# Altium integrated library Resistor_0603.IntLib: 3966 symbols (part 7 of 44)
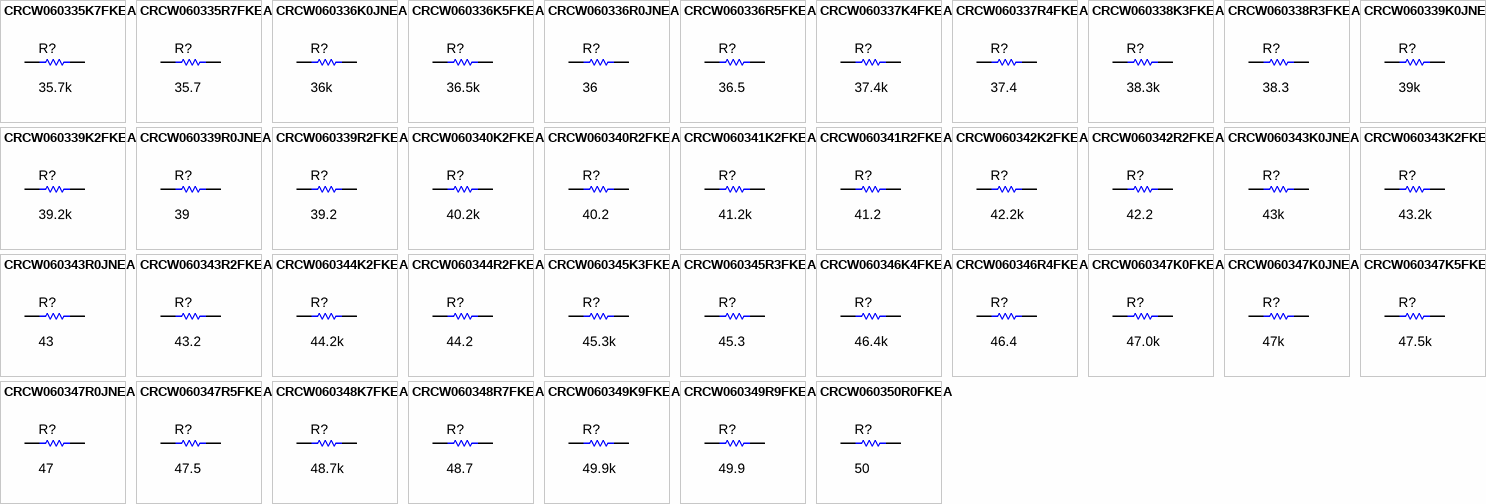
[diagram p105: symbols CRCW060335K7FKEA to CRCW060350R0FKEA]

## CRCW060342K2FKEA
designator R?  ValueDisplayed: 42.2k  (hidden comment: CRCW060342K2FKEA)
RES, 42.2 k, 1%, 0.1 W, 0603; Manufacturer: Vishay-Dale; CompType: Resistor; Value: 42.2k; Res_ohm: 42200; Value_Code: 42k2; Tolerance_%: 1; Power_W: 0.1; Value2: 0.1W; VDC_V: 75; TempCo: 100 ppm/C; SizeArea_mm2: 1.28; SizeX_mm: 1.6; SizeY_mm: 0.8; EIA_Code: E96; U/M: EA; AEC Category: Q200; Green_Lifecycle: Active; Green_REACh: Passed
signal-integrity model Resistor
simulation model Resistor
footprint 0603
footprint 0603M
footprint 0603L
footprint 0603_HV
footprint 0603S
pins: 1, 2

## CRCW060342R2FKEA
designator R?  ValueDisplayed: 42.2  (hidden comment: CRCW060342R2FKEA)
RES, 42.2, 1%, 0.1 W, 0603; Manufacturer: Vishay-Dale; CompType: Resistor; Value: 42.2; Value_Code: 42R2; Tolerance_%: 1; Power_W: 0.1; Value2: 0.1W; VDC_V: 75; TempCo: 100 ppm/C; SizeArea_mm2: 1.28; SizeX_mm: 1.6; SizeY_mm: 0.8; EIA_Code: E96; U/M: EA; AEC Category: Q200
signal-integrity model Resistor
simulation model Resistor
footprint 0603
footprint 0603M
footprint 0603L
footprint 0603_HV
footprint 0603S
pins: 1, 2

## CRCW060343K0JNEA
designator R?  ValueDisplayed: 43k  (hidden comment: CRCW060343K0JNEA)
RES, 43 k, 5%, 0.1 W, 0603; Manufacturer: Vishay-Dale; CompType: Resistor; Value: 43k; Res_ohm: 43000; Value_Code: 43k0; Tolerance_%: 5; Power_W: 0.1; Value2: 0.1W; VDC_V: 75; TempCo: 200 ppm/C; SizeArea_mm2: 1.28; SizeX_mm: 1.6; SizeY_mm: 0.8; SizeZ_mm: 1; EIA_Code: E24; U/M: EA; AEC Category: Q200
signal-integrity model Resistor
simulation model Resistor
footprint 0603
footprint 0603M
footprint 0603L
footprint 0603_HV
footprint 0603S
pins: 1, 2

## CRCW060343K2FKEA
designator R?  ValueDisplayed: 43.2k  (hidden comment: CRCW060343K2FKEA)
RES, 43.2 k, 1%, 0.1 W, 0603; Manufacturer: Vishay-Dale; CompType: Resistor; Value: 43.2k; Res_ohm: 43200; Value_Code: 43k2; Tolerance_%: 1; Power_W: 0.1; Value2: 0.1W; VDC_V: 75; TempCo: 100 ppm/C; SizeArea_mm2: 1.28; SizeX_mm: 1.6; SizeY_mm: 0.8; EIA_Code: E96; U/M: EA; AEC Category: Q200; Green_Lifecycle: Active; Green_REACh: Passed
signal-integrity model Resistor
simulation model Resistor
footprint 0603
footprint 0603M
footprint 0603L
footprint 0603_HV
footprint 0603S
pins: 1, 2

## CRCW060343R0JNEA
designator R?  ValueDisplayed: 43  (hidden comment: CRCW060343R0JNEA)
RES, 43, 5%, 0.1 W, 0603; Manufacturer: Vishay-Dale; CompType: Resistor; Value: 43; Value_Code: 43R0; Tolerance_%: 5; Power_W: 0.1; Value2: 0.1W; VDC_V: 75; TempCo: 200 ppm/C; SizeArea_mm2: 1.28; SizeX_mm: 1.6; SizeY_mm: 0.8; SizeZ_mm: 1; EIA_Code: E24; U/M: EA; AEC Category: Q200; Green_Lifecycle: Active; Green_REACh: Passed
signal-integrity model Resistor
simulation model Resistor
footprint 0603
footprint 0603M
footprint 0603L
footprint 0603_HV
footprint 0603S
pins: 1, 2

## CRCW060343R2FKEA
designator R?  ValueDisplayed: 43.2  (hidden comment: CRCW060343R2FKEA)
RES, 43.2, 1%, 0.1 W, 0603; Manufacturer: Vishay-Dale; CompType: Resistor; Value: 43.2; Value_Code: 43R2; Tolerance_%: 1; Power_W: 0.1; Value2: 0.1W; VDC_V: 75; TempCo: 100 ppm/C; SizeArea_mm2: 1.28; SizeX_mm: 1.6; SizeY_mm: 0.8; EIA_Code: E96; U/M: EA; AEC Category: Q200; Green_Lifecycle: Active; Green_REACh: Passed
signal-integrity model Resistor
simulation model Resistor
footprint 0603
footprint 0603M
footprint 0603L
footprint 0603_HV
footprint 0603S
pins: 1, 2

## CRCW060344K2FKEA
designator R?  ValueDisplayed: 44.2k  (hidden comment: CRCW060344K2FKEA)
RES, 44.2 k, 1%, 0.1 W, 0603; Manufacturer: Vishay-Dale; CompType: Resistor; Value: 44.2k; Res_ohm: 44200; Value_Code: 44k2; Tolerance_%: 1; Power_W: 0.1; Value2: 0.1W; VDC_V: 75; TempCo: 100 ppm/C; SizeArea_mm2: 1.28; SizeX_mm: 1.6; SizeY_mm: 0.8; EIA_Code: E96; U/M: EA; AEC Category: Q200; Green_Lifecycle: Active; Green_REACh: Passed
signal-integrity model Resistor
simulation model Resistor
footprint 0603
footprint 0603M
footprint 0603L
footprint 0603_HV
footprint 0603S
pins: 1, 2

## CRCW060344R2FKEA
designator R?  ValueDisplayed: 44.2  (hidden comment: CRCW060344R2FKEA)
RES, 44.2, 1%, 0.1 W, 0603; Manufacturer: Vishay-Dale; CompType: Resistor; Value: 44.2; Value_Code: 44R2; Tolerance_%: 1; Power_W: 0.1; Value2: 0.1W; VDC_V: 75; TempCo: 100 ppm/C; SizeArea_mm2: 1.28; SizeX_mm: 1.6; SizeY_mm: 0.8; EIA_Code: E96; U/M: EA; AEC Category: Q200
signal-integrity model Resistor
simulation model Resistor
footprint 0603
footprint 0603M
footprint 0603L
footprint 0603_HV
footprint 0603S
pins: 1, 2

## CRCW060345K3FKEA
designator R?  ValueDisplayed: 45.3k  (hidden comment: CRCW060345K3FKEA)
RES, 45.3 k, 1%, 0.1 W, 0603; Manufacturer: Vishay-Dale; CompType: Resistor; Value: 45.3k; Res_ohm: 45300; Value_Code: 45k3; Tolerance_%: 1; Power_W: 0.1; Value2: 0.1W; VDC_V: 75; TempCo: 100 ppm/C; SizeArea_mm2: 1.28; SizeX_mm: 1.6; SizeY_mm: 0.8; EIA_Code: E96; U/M: EA; AEC Category: Q200; Green_Lifecycle: Active; Green_REACh: Passed
signal-integrity model Resistor
simulation model Resistor
footprint 0603
footprint 0603M
footprint 0603L
footprint 0603_HV
footprint 0603S
pins: 1, 2

## CRCW060345R3FKEA
designator R?  ValueDisplayed: 45.3  (hidden comment: CRCW060345R3FKEA)
RES, 45.3, 1%, 0.1 W, 0603; Manufacturer: Vishay-Dale; CompType: Resistor; Value: 45.3; Value_Code: 45R3; Tolerance_%: 1; Power_W: 0.1; Value2: 0.1W; VDC_V: 75; TempCo: 100 ppm/C; SizeArea_mm2: 1.28; SizeX_mm: 1.6; SizeY_mm: 0.8; EIA_Code: E96; U/M: EA; AEC Category: Q200
signal-integrity model Resistor
simulation model Resistor
footprint 0603
footprint 0603M
footprint 0603L
footprint 0603_HV
footprint 0603S
pins: 1, 2

## CRCW060346K4FKEA
designator R?  ValueDisplayed: 46.4k  (hidden comment: CRCW060346K4FKEA)
RES, 46.4 k, 1%, 0.1 W, 0603; Manufacturer: Vishay-Dale; CompType: Resistor; Value: 46.4k; Res_ohm: 46400; Value_Code: 46k4; Tolerance_%: 1; Power_W: 0.1; Value2: 0.1W; VDC_V: 75; TempCo: 100 ppm/C; SizeArea_mm2: 1.28; SizeX_mm: 1.6; SizeY_mm: 0.8; EIA_Code: E96; U/M: EA; AEC Category: Q200; Green_Lifecycle: Active; Green_REACh: Passed
signal-integrity model Resistor
simulation model Resistor
footprint 0603
footprint 0603M
footprint 0603L
footprint 0603_HV
footprint 0603S
pins: 1, 2

## CRCW060346R4FKEA
designator R?  ValueDisplayed: 46.4  (hidden comment: CRCW060346R4FKEA)
RES, 46.4, 1%, 0.1 W, 0603; Manufacturer: Vishay-Dale; CompType: Resistor; Value: 46.4; Value_Code: 46R4; Tolerance_%: 1; Power_W: 0.1; Value2: 0.1W; VDC_V: 75; TempCo: 100 ppm/C; SizeArea_mm2: 1.28; SizeX_mm: 1.6; SizeY_mm: 0.8; EIA_Code: E96; U/M: EA; AEC Category: Q200
signal-integrity model Resistor
simulation model Resistor
footprint 0603
footprint 0603M
footprint 0603L
footprint 0603_HV
footprint 0603S
pins: 1, 2

## CRCW060347K0FKEA
designator R?  ValueDisplayed: 47.0k  (hidden comment: CRCW060347K0FKEA)
RES, 47.0 k, 1%, 0.1 W, AEC-Q200 Grade 0, 0603; Manufacturer: Vishay-Dale; CompType: Resistor; Value: 47.0k; Res_ohm: 47000; Value_Code: 47k0; Tolerance_%: 1; Power_W: 0.1; Value2: 0.1W; VDC_V: 75; TempCo: 100 ppm/C; SizeArea_mm2: 1.28; SizeX_mm: 1.6; SizeY_mm: 0.8; U/M: EA; AEC Category: Q200; AEC Qualified: Y; AEC Grade: 0
signal-integrity model Resistor
simulation model Resistor
footprint 0603
footprint 0603M
footprint 0603L
footprint 0603_HV
footprint 0603S
pins: 1, 2

## CRCW060347K0JNEA
designator R?  ValueDisplayed: 47k  (hidden comment: CRCW060347K0JNEA)
RES, 47 k, 5%, 0.1 W, 0603; Manufacturer: Vishay-Dale; CompType: Resistor; Value: 47k; Res_ohm: 47000; Value_Code: 47k0; Tolerance_%: 5; Power_W: 0.1; Value2: 0.1W; VDC_V: 75; TempCo: 200 ppm/C; SizeArea_mm2: 1.28; SizeX_mm: 1.6; SizeY_mm: 0.8; SizeZ_mm: 1; EIA_Code: E24; U/M: EA; AEC Category: Q200; Green_Lifecycle: Active; Green_REACh: Passed
signal-integrity model Resistor
simulation model Resistor
footprint 0603
footprint 0603M
footprint 0603L
footprint 0603_HV
footprint 0603S
pins: 1, 2

## CRCW060347K5FKEA
designator R?  ValueDisplayed: 47.5k  (hidden comment: CRCW060347K5FKEA)
RES, 47.5 k, 1%, 0.1 W, 0603; Manufacturer: Vishay-Dale; CompType: Resistor; Value: 47.5k; Res_ohm: 47500; Value_Code: 47k5; Tolerance_%: 1; Power_W: 0.1; Value2: 0.1W; VDC_V: 75; TempCo: 100 ppm/C; SizeArea_mm2: 1.28; SizeX_mm: 1.6; SizeY_mm: 0.8; EIA_Code: E96; U/M: EA; AEC Category: Q200; Green_Lifecycle: Active; Green_REACh: Passed
signal-integrity model Resistor
simulation model Resistor
footprint 0603
footprint 0603M
footprint 0603L
footprint 0603_HV
footprint 0603S
pins: 1, 2

## CRCW060347R0JNEA
designator R?  ValueDisplayed: 47  (hidden comment: CRCW060347R0JNEA)
RES, 47, 5%, 0.1 W, 0603; Manufacturer: Vishay-Dale; CompType: Resistor; Value: 47; Value_Code: 47R0; Tolerance_%: 5; Power_W: 0.1; Value2: 0.1W; VDC_V: 75; TempCo: 200 ppm/C; SizeArea_mm2: 1.28; SizeX_mm: 1.6; SizeY_mm: 0.8; SizeZ_mm: 1; EIA_Code: E24; U/M: EA; AEC Category: Q200; Green_Lifecycle: Active; Green_REACh: Passed
signal-integrity model Resistor
simulation model Resistor
footprint 0603
footprint 0603M
footprint 0603L
footprint 0603_HV
footprint 0603S
pins: 1, 2

## CRCW060347R5FKEA
designator R?  ValueDisplayed: 47.5  (hidden comment: CRCW060347R5FKEA)
RES, 47.5, 1%, 0.1 W, 0603; Manufacturer: Vishay-Dale; CompType: Resistor; Value: 47.5; Value_Code: 47R5; Tolerance_%: 1; Power_W: 0.1; Value2: 0.1W; VDC_V: 75; TempCo: 100 ppm/C; SizeArea_mm2: 1.28; SizeX_mm: 1.6; SizeY_mm: 0.8; EIA_Code: E96; U/M: EA; AEC Category: Q200
signal-integrity model Resistor
simulation model Resistor
footprint 0603
footprint 0603M
footprint 0603L
footprint 0603_HV
footprint 0603S
pins: 1, 2

## CRCW060348K7FKEA
designator R?  ValueDisplayed: 48.7k  (hidden comment: CRCW060348K7FKEA)
RES, 48.7 k, 1%, 0.1 W, 0603; Manufacturer: Vishay-Dale; CompType: Resistor; Value: 48.7k; Res_ohm: 48700; Value_Code: 48k7; Tolerance_%: 1; Power_W: 0.1; Value2: 0.1W; VDC_V: 75; TempCo: 100 ppm/C; SizeArea_mm2: 1.28; SizeX_mm: 1.6; SizeY_mm: 0.8; EIA_Code: E96; U/M: EA; AEC Category: Q200; Green_Lifecycle: Active; Green_REACh: Passed
signal-integrity model Resistor
simulation model Resistor
footprint 0603
footprint 0603M
footprint 0603L
footprint 0603_HV
footprint 0603S
pins: 1, 2

## CRCW060348R7FKEA
designator R?  ValueDisplayed: 48.7  (hidden comment: CRCW060348R7FKEA)
RES, 48.7, 1%, 0.1 W, 0603; Manufacturer: Vishay-Dale; CompType: Resistor; Value: 48.7; Value_Code: 48R7; Tolerance_%: 1; Power_W: 0.1; Value2: 0.1W; VDC_V: 75; TempCo: 100 ppm/C; SizeArea_mm2: 1.28; SizeX_mm: 1.6; SizeY_mm: 0.8; EIA_Code: E96; U/M: EA; AEC Category: Q200
signal-integrity model Resistor
simulation model Resistor
footprint 0603
footprint 0603M
footprint 0603L
footprint 0603_HV
footprint 0603S
pins: 1, 2

## CRCW060349K9FKEA
designator R?  ValueDisplayed: 49.9k  (hidden comment: CRCW060349K9FKEA)
RES, 49.9 k, 1%, 0.1 W, 0603; Manufacturer: Vishay-Dale; CompType: Resistor; Value: 49.9k; Res_ohm: 49900; Value_Code: 49k9; Tolerance_%: 1; Power_W: 0.1; Value2: 0.1W; VDC_V: 75; TempCo: 100 ppm/C; SizeArea_mm2: 1.28; SizeX_mm: 1.6; SizeY_mm: 0.8; EIA_Code: E96; U/M: EA; AEC Category: Q200; Green_Lifecycle: Active; Green_REACh: Passed
signal-integrity model Resistor
simulation model Resistor
footprint 0603
footprint 0603M
footprint 0603L
footprint 0603_HV
footprint 0603S
pins: 1, 2

## CRCW060349R9FKEA
designator R?  ValueDisplayed: 49.9  (hidden comment: CRCW060349R9FKEA)
RES, 49.9, 1%, 0.1 W, 0603; Manufacturer: Vishay-Dale; CompType: Resistor; Value: 49.9; Value_Code: 49R9; Tolerance_%: 1; Power_W: 0.1; Value2: 0.1W; VDC_V: 75; TempCo: 100 ppm/C; SizeArea_mm2: 1.28; SizeX_mm: 1.6; SizeY_mm: 0.8; EIA_Code: E96; U/M: EA; AEC Category: Q200; Green_Lifecycle: Active; Green_REACh: Passed
signal-integrity model Resistor
simulation model Resistor
footprint 0603
footprint 0603M
footprint 0603L
footprint 0603_HV
footprint 0603S
pins: 1, 2

## CRCW060350R0FKEA
designator R?  ValueDisplayed: 50  (hidden comment: CRCW060350R0FKEA)
RES, 50, 1%, 0.1 W, 0603; Manufacturer: Vishay-Dale; CompType: Resistor; Value: 50; Value_Code: 50R0; Tolerance_%: 1; Power_W: 0.1; Value2: 0.1W; VDC_V: 75; TempCo: 100 ppm/C; SizeArea_mm2: 1.28; SizeX_mm: 1.6; SizeY_mm: 0.8; U/M: EA; AEC Category: Q200; Green_Lifecycle: Active; Green_REACh: Passed
signal-integrity model Resistor
simulation model Resistor
footprint 0603
footprint 0603M
footprint 0603L
footprint 0603_HV
footprint 0603S
pins: 1, 2

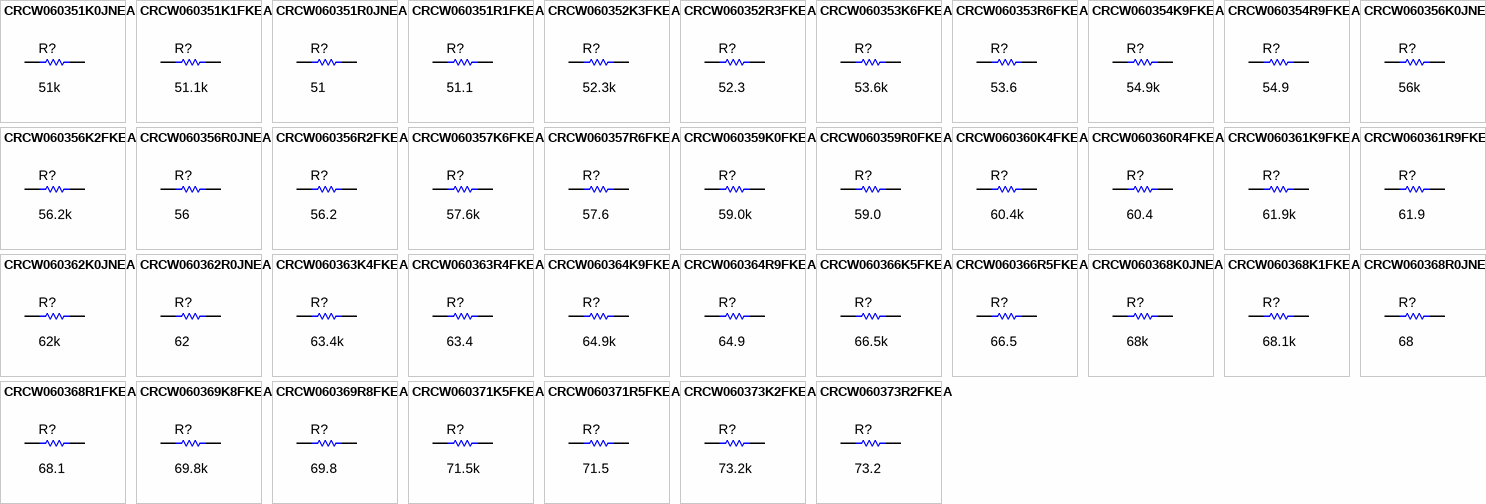
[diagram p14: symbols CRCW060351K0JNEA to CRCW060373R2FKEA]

## CRCW060351K0JNEA
designator R?  ValueDisplayed: 51k  (hidden comment: CRCW060351K0JNEA)
RES, 51 k, 5%, 0.1 W, 0603; Manufacturer: Vishay-Dale; CompType: Resistor; Value: 51k; Res_ohm: 51000; Value_Code: 51k0; Tolerance_%: 5; Power_W: 0.1; Value2: 0.1W; VDC_V: 75; TempCo: 200 ppm/C; SizeArea_mm2: 1.28; SizeX_mm: 1.6; SizeY_mm: 0.8; SizeZ_mm: 1; EIA_Code: E24; U/M: EA; AEC Category: Q200; Green_Lifecycle: Active; Green_REACh: Passed
signal-integrity model Resistor
simulation model Resistor
footprint 0603
footprint 0603M
footprint 0603L
footprint 0603_HV
footprint 0603S
pins: 1, 2

## CRCW060351K1FKEA
designator R?  ValueDisplayed: 51.1k  (hidden comment: CRCW060351K1FKEA)
RES, 51.1 k, 1%, 0.1 W, 0603; Manufacturer: Vishay-Dale; CompType: Resistor; Value: 51.1k; Res_ohm: 51100; Value_Code: 51k1; Tolerance_%: 1; Power_W: 0.1; Value2: 0.1W; VDC_V: 75; TempCo: 100 ppm/C; SizeArea_mm2: 1.28; SizeX_mm: 1.6; SizeY_mm: 0.8; EIA_Code: E96; U/M: EA; AEC Category: Q200; Green_Lifecycle: Active; Green_REACh: Passed
signal-integrity model Resistor
simulation model Resistor
footprint 0603
footprint 0603M
footprint 0603L
footprint 0603_HV
footprint 0603S
pins: 1, 2

## CRCW060351R0JNEA
designator R?  ValueDisplayed: 51  (hidden comment: CRCW060351R0JNEA)
RES, 51, 5%, 0.1 W, 0603; Manufacturer: Vishay-Dale; CompType: Resistor; Value: 51; Value_Code: 51R0; Tolerance_%: 5; Power_W: 0.1; Value2: 0.1W; VDC_V: 75; TempCo: 200 ppm/C; SizeArea_mm2: 1.28; SizeX_mm: 1.6; SizeY_mm: 0.8; SizeZ_mm: 1; EIA_Code: E24; U/M: EA; AEC Category: Q200; Green_Lifecycle: Active; Green_REACh: Passed
signal-integrity model Resistor
simulation model Resistor
footprint 0603
footprint 0603M
footprint 0603L
footprint 0603_HV
footprint 0603S
pins: 1, 2

## CRCW060351R1FKEA
designator R?  ValueDisplayed: 51.1  (hidden comment: CRCW060351R1FKEA)
RES, 51.1, 1%, 0.1 W, 0603; Manufacturer: Vishay-Dale; CompType: Resistor; Value: 51.1; Value_Code: 51R1; Tolerance_%: 1; Power_W: 0.1; Value2: 0.1W; VDC_V: 75; TempCo: 100 ppm/C; SizeArea_mm2: 1.28; SizeX_mm: 1.6; SizeY_mm: 0.8; EIA_Code: E96; U/M: EA; AEC Category: Q200; Green_Lifecycle: Active; Green_REACh: Passed
signal-integrity model Resistor
simulation model Resistor
footprint 0603
footprint 0603M
footprint 0603L
footprint 0603_HV
footprint 0603S
pins: 1, 2

## CRCW060352K3FKEA
designator R?  ValueDisplayed: 52.3k  (hidden comment: CRCW060352K3FKEA)
RES, 52.3 k, 1%, 0.1 W, 0603; Manufacturer: Vishay-Dale; CompType: Resistor; Value: 52.3k; Res_ohm: 52300; Value_Code: 52k3; Tolerance_%: 1; Power_W: 0.1; Value2: 0.1W; VDC_V: 75; TempCo: 100 ppm/C; SizeArea_mm2: 1.28; SizeX_mm: 1.6; SizeY_mm: 0.8; EIA_Code: E96; U/M: EA; AEC Category: Q200; Green_Lifecycle: Active; Green_REACh: Passed
signal-integrity model Resistor
simulation model Resistor
footprint 0603
footprint 0603M
footprint 0603L
footprint 0603_HV
footprint 0603S
pins: 1, 2

## CRCW060352R3FKEA
designator R?  ValueDisplayed: 52.3  (hidden comment: CRCW060352R3FKEA)
RES, 52.3, 1%, 0.1 W, 0603; Manufacturer: Vishay-Dale; CompType: Resistor; Value: 52.3; Value_Code: 52R3; Tolerance_%: 1; Power_W: 0.1; Value2: 0.1W; VDC_V: 75; TempCo: 100 ppm/C; SizeArea_mm2: 1.28; SizeX_mm: 1.6; SizeY_mm: 0.8; EIA_Code: E96; U/M: EA; AEC Category: Q200; Green_Lifecycle: Active; Green_REACh: Passed
signal-integrity model Resistor
simulation model Resistor
footprint 0603
footprint 0603M
footprint 0603L
footprint 0603_HV
footprint 0603S
pins: 1, 2

## CRCW060353K6FKEA
designator R?  ValueDisplayed: 53.6k  (hidden comment: CRCW060353K6FKEA)
RES, 53.6 k, 1%, 0.1 W, 0603; Manufacturer: Vishay-Dale; CompType: Resistor; Value: 53.6k; Res_ohm: 53600; Value_Code: 53k6; Tolerance_%: 1; Power_W: 0.1; Value2: 0.1W; VDC_V: 75; TempCo: 100 ppm/C; SizeArea_mm2: 1.28; SizeX_mm: 1.6; SizeY_mm: 0.8; EIA_Code: E96; U/M: EA; AEC Category: Q200; Green_Lifecycle: Active; Green_REACh: Passed
signal-integrity model Resistor
simulation model Resistor
footprint 0603
footprint 0603M
footprint 0603L
footprint 0603_HV
footprint 0603S
pins: 1, 2

## CRCW060353R6FKEA
designator R?  ValueDisplayed: 53.6  (hidden comment: CRCW060353R6FKEA)
RES, 53.6, 1%, 0.1 W, 0603; Manufacturer: Vishay-Dale; CompType: Resistor; Value: 53.6; Value_Code: 53R6; Tolerance_%: 1; Power_W: 0.1; Value2: 0.1W; VDC_V: 75; TempCo: 100 ppm/C; SizeArea_mm2: 1.28; SizeX_mm: 1.6; SizeY_mm: 0.8; EIA_Code: E96; U/M: EA; AEC Category: Q200; Green_Lifecycle: Active; Green_REACh: Passed
signal-integrity model Resistor
simulation model Resistor
footprint 0603
footprint 0603M
footprint 0603L
footprint 0603_HV
footprint 0603S
pins: 1, 2

## CRCW060354K9FKEA
designator R?  ValueDisplayed: 54.9k  (hidden comment: CRCW060354K9FKEA)
RES, 54.9 k, 1%, 0.1 W, 0603; Manufacturer: Vishay-Dale; CompType: Resistor; Value: 54.9k; Res_ohm: 54900; Value_Code: 54k9; Tolerance_%: 1; Power_W: 0.1; Value2: 0.1W; VDC_V: 75; TempCo: 100 ppm/C; SizeArea_mm2: 1.28; SizeX_mm: 1.6; SizeY_mm: 0.8; EIA_Code: E96; U/M: EA; AEC Category: Q200; Green_Lifecycle: Active; Green_REACh: Passed
signal-integrity model Resistor
simulation model Resistor
footprint 0603
footprint 0603M
footprint 0603L
footprint 0603_HV
footprint 0603S
pins: 1, 2

## CRCW060354R9FKEA
designator R?  ValueDisplayed: 54.9  (hidden comment: CRCW060354R9FKEA)
RES, 54.9, 1%, 0.1 W, 0603; Manufacturer: Vishay-Dale; CompType: Resistor; Value: 54.9; Value_Code: 54R9; Tolerance_%: 1; Power_W: 0.1; Value2: 0.1W; VDC_V: 75; TempCo: 100 ppm/C; SizeArea_mm2: 1.28; SizeX_mm: 1.6; SizeY_mm: 0.8; EIA_Code: E96; U/M: EA; AEC Category: Q200; Green_Lifecycle: Active; Green_REACh: Passed
signal-integrity model Resistor
simulation model Resistor
footprint 0603
footprint 0603M
footprint 0603L
footprint 0603_HV
footprint 0603S
pins: 1, 2

## CRCW060356K0JNEA
designator R?  ValueDisplayed: 56k  (hidden comment: CRCW060356K0JNEA)
RES, 56 k, 5%, 0.1 W, 0603; Manufacturer: Vishay-Dale; CompType: Resistor; Value: 56k; Res_ohm: 56000; Value_Code: 56k0; Tolerance_%: 5; Power_W: 0.1; Value2: 0.1W; VDC_V: 75; TempCo: 200 ppm/C; SizeArea_mm2: 1.28; SizeX_mm: 1.6; SizeY_mm: 0.8; SizeZ_mm: 1; EIA_Code: E24; U/M: EA; AEC Category: Q200
signal-integrity model Resistor
simulation model Resistor
footprint 0603
footprint 0603M
footprint 0603L
footprint 0603_HV
footprint 0603S
pins: 1, 2

## CRCW060356K2FKEA
designator R?  ValueDisplayed: 56.2k  (hidden comment: CRCW060356K2FKEA)
RES, 56.2 k, 1%, 0.1 W, 0603; Manufacturer: Vishay-Dale; CompType: Resistor; Value: 56.2k; Res_ohm: 56200; Value_Code: 56k2; Tolerance_%: 1; Power_W: 0.1; Value2: 0.1W; VDC_V: 75; TempCo: 100 ppm/C; SizeArea_mm2: 1.28; SizeX_mm: 1.6; SizeY_mm: 0.8; EIA_Code: E96; U/M: EA; AEC Category: Q200; Green_Lifecycle: Active; Green_REACh: Passed
signal-integrity model Resistor
simulation model Resistor
footprint 0603
footprint 0603M
footprint 0603L
footprint 0603_HV
footprint 0603S
pins: 1, 2

## CRCW060356R0JNEA
designator R?  ValueDisplayed: 56  (hidden comment: CRCW060356R0JNEA)
RES, 56, 5%, 0.1 W, 0603; Manufacturer: Vishay-Dale; CompType: Resistor; Value: 56; Value_Code: 56R0; Tolerance_%: 5; Power_W: 0.1; Value2: 0.1W; VDC_V: 75; TempCo: 200 ppm/C; SizeArea_mm2: 1.28; SizeX_mm: 1.6; SizeY_mm: 0.8; SizeZ_mm: 1; EIA_Code: E24; U/M: EA; AEC Category: Q200; Green_Lifecycle: Active; Green_REACh: Passed
signal-integrity model Resistor
simulation model Resistor
footprint 0603
footprint 0603M
footprint 0603L
footprint 0603_HV
footprint 0603S
pins: 1, 2

## CRCW060356R2FKEA
designator R?  ValueDisplayed: 56.2  (hidden comment: CRCW060356R2FKEA)
RES, 56.2, 1%, 0.1 W, 0603; Manufacturer: Vishay-Dale; CompType: Resistor; Value: 56.2; Value_Code: 56R2; Tolerance_%: 1; Power_W: 0.1; Value2: 0.1W; VDC_V: 75; TempCo: 100 ppm/C; SizeArea_mm2: 1.28; SizeX_mm: 1.6; SizeY_mm: 0.8; EIA_Code: E96; U/M: EA; AEC Category: Q200; Green_Lifecycle: Active; Green_REACh: Passed
signal-integrity model Resistor
simulation model Resistor
footprint 0603
footprint 0603M
footprint 0603L
footprint 0603_HV
footprint 0603S
pins: 1, 2

## CRCW060357K6FKEA
designator R?  ValueDisplayed: 57.6k  (hidden comment: CRCW060357K6FKEA)
RES, 57.6 k, 1%, 0.1 W, 0603; Manufacturer: Vishay-Dale; CompType: Resistor; Value: 57.6k; Res_ohm: 57600; Value_Code: 57k6; Tolerance_%: 1; Power_W: 0.1; Value2: 0.1W; VDC_V: 75; TempCo: 100 ppm/C; SizeArea_mm2: 1.28; SizeX_mm: 1.6; SizeY_mm: 0.8; EIA_Code: E96; U/M: EA; AEC Category: Q200
signal-integrity model Resistor
simulation model Resistor
footprint 0603
footprint 0603M
footprint 0603L
footprint 0603_HV
footprint 0603S
pins: 1, 2

## CRCW060357R6FKEA
designator R?  ValueDisplayed: 57.6  (hidden comment: CRCW060357R6FKEA)
RES, 57.6, 1%, 0.1 W, 0603; Manufacturer: Vishay-Dale; CompType: Resistor; Value: 57.6; Value_Code: 57R6; Tolerance_%: 1; Power_W: 0.1; Value2: 0.1W; VDC_V: 75; TempCo: 100 ppm/C; SizeArea_mm2: 1.28; SizeX_mm: 1.6; SizeY_mm: 0.8; EIA_Code: E96; U/M: EA; AEC Category: Q200
signal-integrity model Resistor
simulation model Resistor
footprint 0603
footprint 0603M
footprint 0603L
footprint 0603_HV
footprint 0603S
pins: 1, 2

## CRCW060359K0FKEA
designator R?  ValueDisplayed: 59.0k  (hidden comment: CRCW060359K0FKEA)
RES, 59.0 k, 1%, 0.1 W, 0603; Manufacturer: Vishay-Dale; CompType: Resistor; Value: 59.0k; Res_ohm: 59000; Value_Code: 59k0; Tolerance_%: 1; Power_W: 0.1; Value2: 0.1W; VDC_V: 75; TempCo: 100 ppm/C; SizeArea_mm2: 1.28; SizeX_mm: 1.6; SizeY_mm: 0.8; EIA_Code: E96; U/M: EA; AEC Category: Q200; Green_Lifecycle: Active; Green_REACh: Passed
signal-integrity model Resistor
simulation model Resistor
footprint 0603
footprint 0603M
footprint 0603L
footprint 0603_HV
footprint 0603S
pins: 1, 2

## CRCW060359R0FKEA
designator R?  ValueDisplayed: 59.0  (hidden comment: CRCW060359R0FKEA)
RES, 59.0, 1%, 0.1 W, 0603; Manufacturer: Vishay-Dale; CompType: Resistor; Value: 59.0; Res_ohm: 59; Value_Code: 59R0; Tolerance_%: 1; Power_W: 0.1; Value2: 0.1W; VDC_V: 75; TempCo: 100 ppm/C; SizeArea_mm2: 1.28; SizeX_mm: 1.6; SizeY_mm: 0.8; EIA_Code: E96; U/M: EA; AEC Category: Q200
signal-integrity model Resistor
simulation model Resistor
footprint 0603
footprint 0603M
footprint 0603L
footprint 0603_HV
footprint 0603S
pins: 1, 2

## CRCW060360K4FKEA
designator R?  ValueDisplayed: 60.4k  (hidden comment: CRCW060360K4FKEA)
RES, 60.4 k, 1%, 0.1 W, 0603; Manufacturer: Vishay-Dale; CompType: Resistor; Value: 60.4k; Res_ohm: 60400; Value_Code: 60k4; Tolerance_%: 1; Power_W: 0.1; Value2: 0.1W; VDC_V: 75; TempCo: 100 ppm/C; SizeArea_mm2: 1.28; SizeX_mm: 1.6; SizeY_mm: 0.8; EIA_Code: E96; U/M: EA; AEC Category: Q200; Green_Lifecycle: Active; Green_REACh: Passed
signal-integrity model Resistor
simulation model Resistor
footprint 0603
footprint 0603M
footprint 0603L
footprint 0603_HV
footprint 0603S
pins: 1, 2

## CRCW060360R4FKEA
designator R?  ValueDisplayed: 60.4  (hidden comment: CRCW060360R4FKEA)
RES, 60.4, 1%, 0.1 W, 0603; Manufacturer: Vishay-Dale; CompType: Resistor; Value: 60.4; Value_Code: 60R4; Tolerance_%: 1; Power_W: 0.1; Value2: 0.1W; VDC_V: 75; TempCo: 100 ppm/C; SizeArea_mm2: 1.28; SizeX_mm: 1.6; SizeY_mm: 0.8; EIA_Code: E96; U/M: EA; AEC Category: Q200
signal-integrity model Resistor
simulation model Resistor
footprint 0603
footprint 0603M
footprint 0603L
footprint 0603_HV
footprint 0603S
pins: 1, 2

## CRCW060361K9FKEA
designator R?  ValueDisplayed: 61.9k  (hidden comment: CRCW060361K9FKEA)
RES, 61.9 k, 1%, 0.1 W, 0603; Manufacturer: Vishay-Dale; CompType: Resistor; Value: 61.9k; Res_ohm: 61900; Value_Code: 61k9; Tolerance_%: 1; Power_W: 0.1; Value2: 0.1W; VDC_V: 75; TempCo: 100 ppm/C; SizeArea_mm2: 1.28; SizeX_mm: 1.6; SizeY_mm: 0.8; EIA_Code: E96; U/M: EA; AEC Category: Q200; Green_Lifecycle: Active; Green_REACh: Passed
signal-integrity model Resistor
simulation model Resistor
footprint 0603
footprint 0603M
footprint 0603L
footprint 0603_HV
footprint 0603S
pins: 1, 2

## CRCW060361R9FKEA
designator R?  ValueDisplayed: 61.9  (hidden comment: CRCW060361R9FKEA)
RES, 61.9, 1%, 0.1 W, 0603; Manufacturer: Vishay-Dale; CompType: Resistor; Value: 61.9; Value_Code: 61R9; Tolerance_%: 1; Power_W: 0.1; Value2: 0.1W; VDC_V: 75; TempCo: 100 ppm/C; SizeArea_mm2: 1.28; SizeX_mm: 1.6; SizeY_mm: 0.8; EIA_Code: E96; U/M: EA; AEC Category: Q200
signal-integrity model Resistor
simulation model Resistor
footprint 0603
footprint 0603M
footprint 0603L
footprint 0603_HV
footprint 0603S
pins: 1, 2

## CRCW060362K0JNEA
designator R?  ValueDisplayed: 62k  (hidden comment: CRCW060362K0JNEA)
RES, 62 k, 5%, 0.1 W, 0603; Manufacturer: Vishay-Dale; CompType: Resistor; Value: 62k; Res_ohm: 62000; Value_Code: 62k0; Tolerance_%: 5; Power_W: 0.1; Value2: 0.1W; VDC_V: 75; TempCo: 200 ppm/C; SizeArea_mm2: 1.28; SizeX_mm: 1.6; SizeY_mm: 0.8; SizeZ_mm: 1; EIA_Code: E24; U/M: EA; AEC Category: Q200
signal-integrity model Resistor
simulation model Resistor
footprint 0603
footprint 0603M
footprint 0603L
footprint 0603_HV
footprint 0603S
pins: 1, 2

## CRCW060362R0JNEA
designator R?  ValueDisplayed: 62  (hidden comment: CRCW060362R0JNEA)
RES, 62, 5%, 0.1 W, 0603; Manufacturer: Vishay-Dale; CompType: Resistor; Value: 62; Value_Code: 62R0; Tolerance_%: 5; Power_W: 0.1; Value2: 0.1W; VDC_V: 75; TempCo: 200 ppm/C; SizeArea_mm2: 1.28; SizeX_mm: 1.6; SizeY_mm: 0.8; SizeZ_mm: 1; EIA_Code: E24; U/M: EA; AEC Category: Q200
signal-integrity model Resistor
simulation model Resistor
footprint 0603
footprint 0603M
footprint 0603L
footprint 0603_HV
footprint 0603S
pins: 1, 2

## CRCW060363K4FKEA
designator R?  ValueDisplayed: 63.4k  (hidden comment: CRCW060363K4FKEA)
RES, 63.4 k, 1%, 0.1 W, 0603; Manufacturer: Vishay-Dale; CompType: Resistor; Value: 63.4k; Res_ohm: 63400; Value_Code: 63k4; Tolerance_%: 1; Power_W: 0.1; Value2: 0.1W; VDC_V: 75; TempCo: 100 ppm/C; SizeArea_mm2: 1.28; SizeX_mm: 1.6; SizeY_mm: 0.8; EIA_Code: E96; U/M: EA; AEC Category: Q200
signal-integrity model Resistor
simulation model Resistor
footprint 0603
footprint 0603M
footprint 0603L
footprint 0603_HV
footprint 0603S
pins: 1, 2

## CRCW060363R4FKEA
designator R?  ValueDisplayed: 63.4  (hidden comment: CRCW060363R4FKEA)
RES, 63.4, 1%, 0.1 W, 0603; Manufacturer: Vishay-Dale; CompType: Resistor; Value: 63.4; Value_Code: 63R4; Tolerance_%: 1; Power_W: 0.1; Value2: 0.1W; VDC_V: 75; TempCo: 100 ppm/C; SizeArea_mm2: 1.28; SizeX_mm: 1.6; SizeY_mm: 0.8; EIA_Code: E96; U/M: EA; AEC Category: Q200
signal-integrity model Resistor
simulation model Resistor
footprint 0603
footprint 0603M
footprint 0603L
footprint 0603_HV
footprint 0603S
pins: 1, 2

## CRCW060364K9FKEA
designator R?  ValueDisplayed: 64.9k  (hidden comment: CRCW060364K9FKEA)
RES, 64.9 k, 1%, 0.1 W, 0603; Manufacturer: Vishay-Dale; CompType: Resistor; Value: 64.9k; Res_ohm: 64900; Value_Code: 64k9; Tolerance_%: 1; Power_W: 0.1; Value2: 0.1W; VDC_V: 75; TempCo: 100 ppm/C; SizeArea_mm2: 1.28; SizeX_mm: 1.6; SizeY_mm: 0.8; EIA_Code: E96; U/M: EA; AEC Category: Q200; Green_Lifecycle: Active; Green_REACh: Passed
signal-integrity model Resistor
simulation model Resistor
footprint 0603
footprint 0603M
footprint 0603L
footprint 0603_HV
footprint 0603S
pins: 1, 2

## CRCW060364R9FKEA
designator R?  ValueDisplayed: 64.9  (hidden comment: CRCW060364R9FKEA)
RES, 64.9, 1%, 0.1 W, 0603; Manufacturer: Vishay-Dale; CompType: Resistor; Value: 64.9; Value_Code: 64R9; Tolerance_%: 1; Power_W: 0.1; Value2: 0.1W; VDC_V: 75; TempCo: 100 ppm/C; SizeArea_mm2: 1.28; SizeX_mm: 1.6; SizeY_mm: 0.8; EIA_Code: E96; U/M: EA; AEC Category: Q200
signal-integrity model Resistor
simulation model Resistor
footprint 0603
footprint 0603M
footprint 0603L
footprint 0603_HV
footprint 0603S
pins: 1, 2

## CRCW060366K5FKEA
designator R?  ValueDisplayed: 66.5k  (hidden comment: CRCW060366K5FKEA)
RES, 66.5 k, 1%, 0.1 W, 0603; Manufacturer: Vishay-Dale; CompType: Resistor; Value: 66.5k; Res_ohm: 66500; Value_Code: 66k5; Tolerance_%: 1; Power_W: 0.1; Value2: 0.1W; VDC_V: 75; TempCo: 100 ppm/C; SizeArea_mm2: 1.28; SizeX_mm: 1.6; SizeY_mm: 0.8; EIA_Code: E96; U/M: EA; AEC Category: Q200; Green_Lifecycle: Active; Green_REACh: Passed
signal-integrity model Resistor
simulation model Resistor
footprint 0603
footprint 0603M
footprint 0603L
footprint 0603_HV
footprint 0603S
pins: 1, 2

## CRCW060366R5FKEA
designator R?  ValueDisplayed: 66.5  (hidden comment: CRCW060366R5FKEA)
RES, 66.5, 1%, 0.1 W, 0603; Manufacturer: Vishay-Dale; CompType: Resistor; Value: 66.5; Value_Code: 66R5; Tolerance_%: 1; Power_W: 0.1; Value2: 0.1W; VDC_V: 75; TempCo: 100 ppm/C; SizeArea_mm2: 1.28; SizeX_mm: 1.6; SizeY_mm: 0.8; EIA_Code: E96; U/M: EA; AEC Category: Q200
signal-integrity model Resistor
simulation model Resistor
footprint 0603
footprint 0603M
footprint 0603L
footprint 0603_HV
footprint 0603S
pins: 1, 2

## CRCW060368K0JNEA
designator R?  ValueDisplayed: 68k  (hidden comment: CRCW060368K0JNEA)
RES, 68 k, 5%, 0.1 W, 0603; Manufacturer: Vishay-Dale; CompType: Resistor; Value: 68k; Res_ohm: 68000; Value_Code: 68k0; Tolerance_%: 5; Power_W: 0.1; Value2: 0.1W; VDC_V: 75; TempCo: 200 ppm/C; SizeArea_mm2: 1.28; SizeX_mm: 1.6; SizeY_mm: 0.8; SizeZ_mm: 1; EIA_Code: E24; U/M: EA; AEC Category: Q200; Green_Lifecycle: Active; Green_REACh: Passed
signal-integrity model Resistor
simulation model Resistor
footprint 0603
footprint 0603M
footprint 0603L
footprint 0603_HV
footprint 0603S
pins: 1, 2

## CRCW060368K1FKEA
designator R?  ValueDisplayed: 68.1k  (hidden comment: CRCW060368K1FKEA)
RES, 68.1 k, 1%, 0.1 W, 0603; Manufacturer: Vishay-Dale; CompType: Resistor; Value: 68.1k; Res_ohm: 68100; Value_Code: 68k1; Tolerance_%: 1; Power_W: 0.1; Value2: 0.1W; VDC_V: 75; TempCo: 100 ppm/C; SizeArea_mm2: 1.28; SizeX_mm: 1.6; SizeY_mm: 0.8; EIA_Code: E96; U/M: EA; AEC Category: Q200; Green_Lifecycle: Active; Green_REACh: Passed
signal-integrity model Resistor
simulation model Resistor
footprint 0603
footprint 0603M
footprint 0603L
footprint 0603_HV
footprint 0603S
pins: 1, 2

## CRCW060368R0JNEA
designator R?  ValueDisplayed: 68  (hidden comment: CRCW060368R0JNEA)
RES, 68, 5%, 0.1 W, 0603; Manufacturer: Vishay-Dale; CompType: Resistor; Value: 68; Value_Code: 68R0; Tolerance_%: 5; Power_W: 0.1; Value2: 0.1W; VDC_V: 75; TempCo: 200 ppm/C; SizeArea_mm2: 1.28; SizeX_mm: 1.6; SizeY_mm: 0.8; SizeZ_mm: 1; EIA_Code: E24; U/M: EA; AEC Category: Q200; Green_Lifecycle: Active; Green_REACh: Passed
signal-integrity model Resistor
simulation model Resistor
footprint 0603
footprint 0603M
footprint 0603L
footprint 0603_HV
footprint 0603S
pins: 1, 2

## CRCW060368R1FKEA
designator R?  ValueDisplayed: 68.1  (hidden comment: CRCW060368R1FKEA)
RES, 68.1, 1%, 0.1 W, 0603; Manufacturer: Vishay-Dale; CompType: Resistor; Value: 68.1; Value_Code: 68R1; Tolerance_%: 1; Power_W: 0.1; Value2: 0.1W; VDC_V: 75; TempCo: 100 ppm/C; SizeArea_mm2: 1.28; SizeX_mm: 1.6; SizeY_mm: 0.8; EIA_Code: E96; U/M: EA; AEC Category: Q200; Green_Lifecycle: Active; Green_REACh: Passed
signal-integrity model Resistor
simulation model Resistor
footprint 0603
footprint 0603M
footprint 0603L
footprint 0603_HV
footprint 0603S
pins: 1, 2

## CRCW060369K8FKEA
designator R?  ValueDisplayed: 69.8k  (hidden comment: CRCW060369K8FKEA)
RES, 69.8 k, 1%, 0.1 W, 0603; Manufacturer: Vishay-Dale; CompType: Resistor; Value: 69.8k; Res_ohm: 69800; Value_Code: 69k8; Tolerance_%: 1; Power_W: 0.1; Value2: 0.1W; VDC_V: 75; TempCo: 100 ppm/C; SizeArea_mm2: 1.28; SizeX_mm: 1.6; SizeY_mm: 0.8; EIA_Code: E96; U/M: EA; AEC Category: Q200; Green_Lifecycle: Active; Green_REACh: Passed
signal-integrity model Resistor
simulation model Resistor
footprint 0603
footprint 0603M
footprint 0603L
footprint 0603_HV
footprint 0603S
pins: 1, 2

## CRCW060369R8FKEA
designator R?  ValueDisplayed: 69.8  (hidden comment: CRCW060369R8FKEA)
RES, 69.8, 1%, 0.1 W, 0603; Manufacturer: Vishay-Dale; CompType: Resistor; Value: 69.8; Value_Code: 69R8; Tolerance_%: 1; Power_W: 0.1; Value2: 0.1W; VDC_V: 75; TempCo: 100 ppm/C; SizeArea_mm2: 1.28; SizeX_mm: 1.6; SizeY_mm: 0.8; EIA_Code: E96; U/M: EA; AEC Category: Q200
signal-integrity model Resistor
simulation model Resistor
footprint 0603
footprint 0603M
footprint 0603L
footprint 0603_HV
footprint 0603S
pins: 1, 2

## CRCW060371K5FKEA
designator R?  ValueDisplayed: 71.5k  (hidden comment: CRCW060371K5FKEA)
RES, 71.5 k, 1%, 0.1 W, 0603; Manufacturer: Vishay-Dale; CompType: Resistor; Value: 71.5k; Res_ohm: 71500; Value_Code: 71k5; Tolerance_%: 1; Power_W: 0.1; Value2: 0.1W; VDC_V: 75; TempCo: 100 ppm/C; SizeArea_mm2: 1.28; SizeX_mm: 1.6; SizeY_mm: 0.8; EIA_Code: E96; U/M: EA; AEC Category: Q200; Green_Lifecycle: Active; Green_REACh: Passed
signal-integrity model Resistor
simulation model Resistor
footprint 0603
footprint 0603M
footprint 0603L
footprint 0603_HV
footprint 0603S
pins: 1, 2

## CRCW060371R5FKEA
designator R?  ValueDisplayed: 71.5  (hidden comment: CRCW060371R5FKEA)
RES, 71.5, 1%, 0.1 W, 0603; Manufacturer: Vishay-Dale; CompType: Resistor; Value: 71.5; Value_Code: 71R5; Tolerance_%: 1; Power_W: 0.1; Value2: 0.1W; VDC_V: 75; TempCo: 100 ppm/C; SizeArea_mm2: 1.28; SizeX_mm: 1.6; SizeY_mm: 0.8; EIA_Code: E96; U/M: EA; AEC Category: Q200; Green_Lifecycle: Active; Green_REACh: Passed
signal-integrity model Resistor
simulation model Resistor
footprint 0603
footprint 0603M
footprint 0603L
footprint 0603_HV
footprint 0603S
pins: 1, 2

## CRCW060373K2FKEA
designator R?  ValueDisplayed: 73.2k  (hidden comment: CRCW060373K2FKEA)
RES, 73.2 k, 1%, 0.1 W, 0603; Manufacturer: Vishay-Dale; CompType: Resistor; Value: 73.2k; Res_ohm: 73200; Value_Code: 73k2; Tolerance_%: 1; Power_W: 0.1; Value2: 0.1W; VDC_V: 75; TempCo: 100 ppm/C; SizeArea_mm2: 1.28; SizeX_mm: 1.6; SizeY_mm: 0.8; EIA_Code: E96; U/M: EA; AEC Category: Q200; Green_Lifecycle: Active; Green_REACh: Passed
signal-integrity model Resistor
simulation model Resistor
footprint 0603
footprint 0603M
footprint 0603L
footprint 0603_HV
footprint 0603S
pins: 1, 2

## CRCW060373R2FKEA
designator R?  ValueDisplayed: 73.2  (hidden comment: CRCW060373R2FKEA)
RES, 73.2, 1%, 0.1 W, 0603; Manufacturer: Vishay-Dale; CompType: Resistor; Value: 73.2; Value_Code: 73R2; Tolerance_%: 1; Power_W: 0.1; Value2: 0.1W; VDC_V: 75; TempCo: 100 ppm/C; SizeArea_mm2: 1.28; SizeX_mm: 1.6; SizeY_mm: 0.8; EIA_Code: E96; U/M: EA; AEC Category: Q200; Green_Lifecycle: Active; Green_REACh: Passed
signal-integrity model Resistor
simulation model Resistor
footprint 0603
footprint 0603M
footprint 0603L
footprint 0603_HV
footprint 0603S
pins: 1, 2

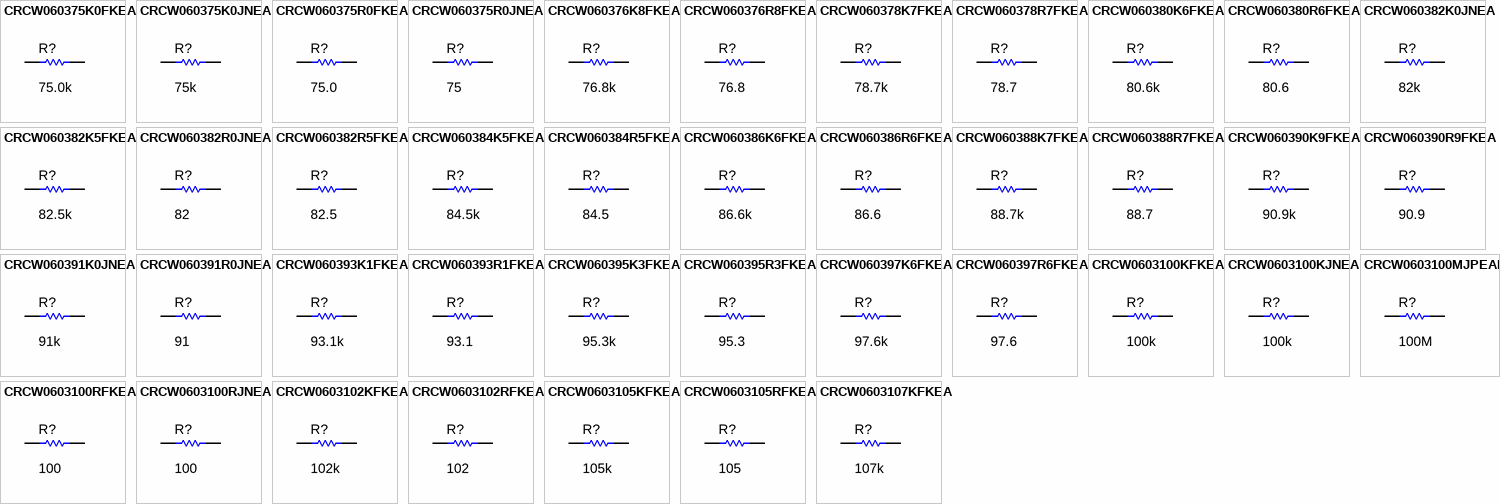
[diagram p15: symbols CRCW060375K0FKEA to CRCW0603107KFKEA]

## CRCW060375K0FKEA
designator R?  ValueDisplayed: 75.0k  (hidden comment: CRCW060375K0FKEA)
RES, 75.0 k, 1%, 0.1 W, 0603; Manufacturer: Vishay-Dale; CompType: Resistor; Value: 75.0k; Res_ohm: 75000; Value_Code: 75k0; Tolerance_%: 1; Power_W: 0.1; Value2: 0.1W; VDC_V: 75; TempCo: 100 ppm/C; SizeArea_mm2: 1.28; SizeX_mm: 1.6; SizeY_mm: 0.8; EIA_Code: E96; U/M: EA; AEC Category: Q200; Green_Lifecycle: Active; Green_REACh: Passed
signal-integrity model Resistor
simulation model Resistor
footprint 0603
footprint 0603M
footprint 0603L
footprint 0603_HV
footprint 0603S
pins: 1, 2

## CRCW060375K0JNEA
designator R?  ValueDisplayed: 75k  (hidden comment: CRCW060375K0JNEA)
RES, 75 k, 5%, 0.1 W, 0603; Manufacturer: Vishay-Dale; CompType: Resistor; Value: 75k; Res_ohm: 75000; Value_Code: 75k0; Tolerance_%: 5; Power_W: 0.1; Value2: 0.1W; VDC_V: 75; TempCo: 200 ppm/C; SizeArea_mm2: 1.28; SizeX_mm: 1.6; SizeY_mm: 0.8; SizeZ_mm: 1; EIA_Code: E24; U/M: EA; AEC Category: Q200
signal-integrity model Resistor
simulation model Resistor
footprint 0603
footprint 0603M
footprint 0603L
footprint 0603_HV
footprint 0603S
pins: 1, 2

## CRCW060375R0FKEA
designator R?  ValueDisplayed: 75.0  (hidden comment: CRCW060375R0FKEA)
RES, 75.0, 1%, 0.1 W, 0603; Manufacturer: Vishay-Dale; CompType: Resistor; Value: 75.0; Res_ohm: 75; Value_Code: 75R0; Tolerance_%: 1; Power_W: 0.1; Value2: 0.1W; TempCo: 100 ppm/C; SizeArea_mm2: 1.28; SizeX_mm: 1.6; SizeY_mm: 0.8; EIA_Code: E96; U/M: EA; AEC Category: Q200; Green_Lifecycle: Active; Green_REACh: Passed
signal-integrity model Resistor
simulation model Resistor
footprint 0603
footprint 0603M
footprint 0603L
footprint 0603_HV
footprint 0603S
pins: 1, 2

## CRCW060375R0JNEA
designator R?  ValueDisplayed: 75  (hidden comment: CRCW060375R0JNEA)
RES, 75, 5%, 0.1 W, 0603; Manufacturer: Vishay-Dale; CompType: Resistor; Value: 75; Value_Code: 75R0; Tolerance_%: 5; Power_W: 0.1; Value2: 0.1W; TempCo: 200 ppm/C; SizeArea_mm2: 1.28; SizeX_mm: 1.6; SizeY_mm: 0.8; SizeZ_mm: 1; EIA_Code: E24; U/M: EA; AEC Category: Q200
signal-integrity model Resistor
simulation model Resistor
footprint 0603
footprint 0603M
footprint 0603L
footprint 0603_HV
footprint 0603S
pins: 1, 2

## CRCW060376K8FKEA
designator R?  ValueDisplayed: 76.8k  (hidden comment: CRCW060376K8FKEA)
RES, 76.8 k, 1%, 0.1 W, 0603; Manufacturer: Vishay-Dale; CompType: Resistor; Value: 76.8k; Res_ohm: 76800; Value_Code: 76k8; Tolerance_%: 1; Power_W: 0.1; Value2: 0.1W; VDC_V: 75; TempCo: 100 ppm/C; SizeArea_mm2: 1.28; SizeX_mm: 1.6; SizeY_mm: 0.8; EIA_Code: E96; U/M: EA; AEC Category: Q200; Green_Lifecycle: Active; Green_REACh: Passed
signal-integrity model Resistor
simulation model Resistor
footprint 0603
footprint 0603M
footprint 0603L
footprint 0603_HV
footprint 0603S
pins: 1, 2

## CRCW060376R8FKEA
designator R?  ValueDisplayed: 76.8  (hidden comment: CRCW060376R8FKEA)
RES, 76.8, 1%, 0.1 W, 0603; Manufacturer: Vishay-Dale; CompType: Resistor; Value: 76.8; Value_Code: 76R8; Tolerance_%: 1; Power_W: 0.1; Value2: 0.1W; VDC_V: 75; TempCo: 100 ppm/C; SizeArea_mm2: 1.28; SizeX_mm: 1.6; SizeY_mm: 0.8; EIA_Code: E96; U/M: EA; AEC Category: Q200
signal-integrity model Resistor
simulation model Resistor
footprint 0603
footprint 0603M
footprint 0603L
footprint 0603_HV
footprint 0603S
pins: 1, 2

## CRCW060378K7FKEA
designator R?  ValueDisplayed: 78.7k  (hidden comment: CRCW060378K7FKEA)
RES, 78.7 k, 1%, 0.1 W, 0603; Manufacturer: Vishay-Dale; CompType: Resistor; Value: 78.7k; Res_ohm: 78700; Value_Code: 78k7; Tolerance_%: 1; Power_W: 0.1; Value2: 0.1W; VDC_V: 75; TempCo: 100 ppm/C; SizeArea_mm2: 1.28; SizeX_mm: 1.6; SizeY_mm: 0.8; EIA_Code: E96; U/M: EA; AEC Category: Q200; Green_Lifecycle: Active; Green_REACh: Passed
signal-integrity model Resistor
simulation model Resistor
footprint 0603
footprint 0603M
footprint 0603L
footprint 0603_HV
footprint 0603S
pins: 1, 2

## CRCW060378R7FKEA
designator R?  ValueDisplayed: 78.7  (hidden comment: CRCW060378R7FKEA)
RES, 78.7, 1%, 0.1 W, 0603; Manufacturer: Vishay-Dale; CompType: Resistor; Value: 78.7; Value_Code: 78R7; Tolerance_%: 1; Power_W: 0.1; Value2: 0.1W; VDC_V: 75; TempCo: 100 ppm/C; SizeArea_mm2: 1.28; SizeX_mm: 1.6; SizeY_mm: 0.8; EIA_Code: E96; U/M: EA; AEC Category: Q200
signal-integrity model Resistor
simulation model Resistor
footprint 0603
footprint 0603M
footprint 0603L
footprint 0603_HV
footprint 0603S
pins: 1, 2

## CRCW060380K6FKEA
designator R?  ValueDisplayed: 80.6k  (hidden comment: CRCW060380K6FKEA)
RES, 80.6 k, 1%, 0.1 W, 0603; Manufacturer: Vishay-Dale; CompType: Resistor; Value: 80.6k; Res_ohm: 80600; Value_Code: 80k6; Tolerance_%: 1; Power_W: 0.1; Value2: 0.1W; VDC_V: 75; TempCo: 100 ppm/C; SizeArea_mm2: 1.28; SizeX_mm: 1.6; SizeY_mm: 0.8; EIA_Code: E96; U/M: EA; AEC Category: Q200; Green_Lifecycle: Active; Green_REACh: Passed
signal-integrity model Resistor
simulation model Resistor
footprint 0603
footprint 0603M
footprint 0603L
footprint 0603_HV
footprint 0603S
pins: 1, 2

## CRCW060380R6FKEA
designator R?  ValueDisplayed: 80.6  (hidden comment: CRCW060380R6FKEA)
RES, 80.6, 1%, 0.1 W, 0603; Manufacturer: Vishay-Dale; CompType: Resistor; Value: 80.6; Value_Code: 80R6; Tolerance_%: 1; Power_W: 0.1; Value2: 0.1W; VDC_V: 75; TempCo: 100 ppm/C; SizeArea_mm2: 1.28; SizeX_mm: 1.6; SizeY_mm: 0.8; EIA_Code: E96; U/M: EA; AEC Category: Q200
signal-integrity model Resistor
simulation model Resistor
footprint 0603
footprint 0603M
footprint 0603L
footprint 0603_HV
footprint 0603S
pins: 1, 2

## CRCW060382K0JNEA
designator R?  ValueDisplayed: 82k  (hidden comment: CRCW060382K0JNEA)
RES, 82 k, 5%, 0.1 W, 0603; Manufacturer: Vishay-Dale; CompType: Resistor; Value: 82k; Res_ohm: 82000; Value_Code: 82k0; Tolerance_%: 5; Power_W: 0.1; Value2: 0.1W; VDC_V: 75; TempCo: 200 ppm/C; SizeArea_mm2: 1.28; SizeX_mm: 1.6; SizeY_mm: 0.8; SizeZ_mm: 1; EIA_Code: E24; U/M: EA; AEC Category: Q200; Green_Lifecycle: Active; Green_REACh: Passed
signal-integrity model Resistor
simulation model Resistor
footprint 0603
footprint 0603M
footprint 0603L
footprint 0603_HV
footprint 0603S
pins: 1, 2

## CRCW060382K5FKEA
designator R?  ValueDisplayed: 82.5k  (hidden comment: CRCW060382K5FKEA)
RES, 82.5 k, 1%, 0.1 W, 0603; Manufacturer: Vishay-Dale; CompType: Resistor; Value: 82.5k; Res_ohm: 82500; Value_Code: 82k5; Tolerance_%: 1; Power_W: 0.1; Value2: 0.1W; VDC_V: 75; TempCo: 100 ppm/C; SizeArea_mm2: 1.28; SizeX_mm: 1.6; SizeY_mm: 0.8; EIA_Code: E96; U/M: EA; AEC Category: Q200; Green_Lifecycle: Active; Green_REACh: Passed
signal-integrity model Resistor
simulation model Resistor
footprint 0603
footprint 0603M
footprint 0603L
footprint 0603_HV
footprint 0603S
pins: 1, 2

## CRCW060382R0JNEA
designator R?  ValueDisplayed: 82  (hidden comment: CRCW060382R0JNEA)
RES, 82, 5%, 0.1 W, 0603; Manufacturer: Vishay-Dale; CompType: Resistor; Value: 82; Value_Code: 82R0; Tolerance_%: 5; Power_W: 0.1; Value2: 0.1W; VDC_V: 75; TempCo: 200 ppm/C; SizeArea_mm2: 1.28; SizeX_mm: 1.6; SizeY_mm: 0.8; SizeZ_mm: 1; EIA_Code: E24; U/M: EA; AEC Category: Q200
signal-integrity model Resistor
simulation model Resistor
footprint 0603
footprint 0603M
footprint 0603L
footprint 0603_HV
footprint 0603S
pins: 1, 2

## CRCW060382R5FKEA
designator R?  ValueDisplayed: 82.5  (hidden comment: CRCW060382R5FKEA)
RES, 82.5, 1%, 0.1 W, 0603; Manufacturer: Vishay-Dale; CompType: Resistor; Value: 82.5; Value_Code: 82R5; Tolerance_%: 1; Power_W: 0.1; Value2: 0.1W; VDC_V: 75; TempCo: 100 ppm/C; SizeArea_mm2: 1.28; SizeX_mm: 1.6; SizeY_mm: 0.8; EIA_Code: E96; U/M: EA; AEC Category: Q200
signal-integrity model Resistor
simulation model Resistor
footprint 0603
footprint 0603M
footprint 0603L
footprint 0603_HV
footprint 0603S
pins: 1, 2

## CRCW060384K5FKEA
designator R?  ValueDisplayed: 84.5k  (hidden comment: CRCW060384K5FKEA)
RES, 84.5 k, 1%, 0.1 W, 0603; Manufacturer: Vishay-Dale; CompType: Resistor; Value: 84.5k; Res_ohm: 84500; Value_Code: 84k5; Tolerance_%: 1; Power_W: 0.1; Value2: 0.1W; VDC_V: 75; TempCo: 100 ppm/C; SizeArea_mm2: 1.28; SizeX_mm: 1.6; SizeY_mm: 0.8; EIA_Code: E96; U/M: EA; AEC Category: Q200; Green_Lifecycle: Active; Green_REACh: Passed
signal-integrity model Resistor
simulation model Resistor
footprint 0603
footprint 0603M
footprint 0603L
footprint 0603_HV
footprint 0603S
pins: 1, 2

## CRCW060384R5FKEA
designator R?  ValueDisplayed: 84.5  (hidden comment: CRCW060384R5FKEA)
RES, 84.5, 1%, 0.1 W, 0603; Manufacturer: Vishay-Dale; CompType: Resistor; Value: 84.5; Value_Code: 84R5; Tolerance_%: 1; Power_W: 0.1; Value2: 0.1W; VDC_V: 75; TempCo: 100 ppm/C; SizeArea_mm2: 1.28; SizeX_mm: 1.6; SizeY_mm: 0.8; EIA_Code: E96; U/M: EA; AEC Category: Q200
signal-integrity model Resistor
simulation model Resistor
footprint 0603
footprint 0603M
footprint 0603L
footprint 0603_HV
footprint 0603S
pins: 1, 2

## CRCW060386K6FKEA
designator R?  ValueDisplayed: 86.6k  (hidden comment: CRCW060386K6FKEA)
RES, 86.6 k, 1%, 0.1 W, 0603; Manufacturer: Vishay-Dale; CompType: Resistor; Value: 86.6k; Res_ohm: 86600; Value_Code: 86k6; Tolerance_%: 1; Power_W: 0.1; Value2: 0.1W; VDC_V: 75; TempCo: 100 ppm/C; SizeArea_mm2: 1.28; SizeX_mm: 1.6; SizeY_mm: 0.8; EIA_Code: E96; U/M: EA; AEC Category: Q200; Green_Lifecycle: Active; Green_REACh: Passed
signal-integrity model Resistor
simulation model Resistor
footprint 0603
footprint 0603M
footprint 0603L
footprint 0603_HV
footprint 0603S
pins: 1, 2

## CRCW060386R6FKEA
designator R?  ValueDisplayed: 86.6  (hidden comment: CRCW060386R6FKEA)
RES, 86.6, 1%, 0.1 W, 0603; Manufacturer: Vishay-Dale; CompType: Resistor; Value: 86.6; Value_Code: 86R6; Tolerance_%: 1; Power_W: 0.1; Value2: 0.1W; VDC_V: 75; TempCo: 100 ppm/C; SizeArea_mm2: 1.28; SizeX_mm: 1.6; SizeY_mm: 0.8; EIA_Code: E96; U/M: EA; AEC Category: Q200
signal-integrity model Resistor
simulation model Resistor
footprint 0603
footprint 0603M
footprint 0603L
footprint 0603_HV
footprint 0603S
pins: 1, 2

## CRCW060388K7FKEA
designator R?  ValueDisplayed: 88.7k  (hidden comment: CRCW060388K7FKEA)
RES, 88.7 k, 1%, 0.1 W, 0603; Manufacturer: Vishay-Dale; CompType: Resistor; Value: 88.7k; Res_ohm: 88700; Value_Code: 88k7; Tolerance_%: 1; Power_W: 0.1; Value2: 0.1W; VDC_V: 75; TempCo: 100 ppm/C; SizeArea_mm2: 1.28; SizeX_mm: 1.6; SizeY_mm: 0.8; EIA_Code: E96; U/M: EA; AEC Category: Q200; Green_Lifecycle: Active; Green_REACh: Passed
signal-integrity model Resistor
simulation model Resistor
footprint 0603
footprint 0603M
footprint 0603L
footprint 0603_HV
footprint 0603S
pins: 1, 2

## CRCW060388R7FKEA
designator R?  ValueDisplayed: 88.7  (hidden comment: CRCW060388R7FKEA)
RES, 88.7, 1%, 0.1 W, 0603; Manufacturer: Vishay-Dale; CompType: Resistor; Value: 88.7; Value_Code: 88R7; Tolerance_%: 1; Power_W: 0.1; Value2: 0.1W; VDC_V: 75; TempCo: 100 ppm/C; SizeArea_mm2: 1.28; SizeX_mm: 1.6; SizeY_mm: 0.8; EIA_Code: E96; U/M: EA; AEC Category: Q200
signal-integrity model Resistor
simulation model Resistor
footprint 0603
footprint 0603M
footprint 0603L
footprint 0603_HV
footprint 0603S
pins: 1, 2

## CRCW060390K9FKEA
designator R?  ValueDisplayed: 90.9k  (hidden comment: CRCW060390K9FKEA)
RES, 90.9 k, 1%, 0.1 W, 0603; Manufacturer: Vishay-Dale; CompType: Resistor; Value: 90.9k; Res_ohm: 90900; Value_Code: 90k9; Tolerance_%: 1; Power_W: 0.1; Value2: 0.1W; VDC_V: 75; TempCo: 100 ppm/C; SizeArea_mm2: 1.28; SizeX_mm: 1.6; SizeY_mm: 0.8; EIA_Code: E96; U/M: EA; AEC Category: Q200; Green_Lifecycle: Active; Green_REACh: Passed
signal-integrity model Resistor
simulation model Resistor
footprint 0603
footprint 0603M
footprint 0603L
footprint 0603_HV
footprint 0603S
pins: 1, 2

## CRCW060390R9FKEA
designator R?  ValueDisplayed: 90.9  (hidden comment: CRCW060390R9FKEA)
RES, 90.9, 1%, 0.1 W, 0603; Manufacturer: Vishay-Dale; CompType: Resistor; Value: 90.9; Value_Code: 90R9; Tolerance_%: 1; Power_W: 0.1; Value2: 0.1W; VDC_V: 75; TempCo: 100 ppm/C; SizeArea_mm2: 1.28; SizeX_mm: 1.6; SizeY_mm: 0.8; EIA_Code: E96; U/M: EA; AEC Category: Q200; Green_Lifecycle: Active; Green_REACh: Passed
signal-integrity model Resistor
simulation model Resistor
footprint 0603
footprint 0603M
footprint 0603L
footprint 0603_HV
footprint 0603S
pins: 1, 2

## CRCW060391K0JNEA
designator R?  ValueDisplayed: 91k  (hidden comment: CRCW060391K0JNEA)
RES, 91 k, 5%, 0.1 W, 0603; Manufacturer: Vishay-Dale; CompType: Resistor; Value: 91k; Res_ohm: 91000; Value_Code: 91k0; Tolerance_%: 5; Power_W: 0.1; Value2: 0.1W; VDC_V: 75; TempCo: 200 ppm/C; SizeArea_mm2: 1.28; SizeX_mm: 1.6; SizeY_mm: 0.8; SizeZ_mm: 1; EIA_Code: E24; U/M: EA; AEC Category: Q200
signal-integrity model Resistor
simulation model Resistor
footprint 0603
footprint 0603M
footprint 0603L
footprint 0603_HV
footprint 0603S
pins: 1, 2

## CRCW060391R0JNEA
designator R?  ValueDisplayed: 91  (hidden comment: CRCW060391R0JNEA)
RES, 91, 5%, 0.1 W, 0603; Manufacturer: Vishay-Dale; CompType: Resistor; Value: 91; Value_Code: 91R0; Tolerance_%: 5; Power_W: 0.1; Value2: 0.1W; VDC_V: 75; TempCo: 200 ppm/C; SizeArea_mm2: 1.28; SizeX_mm: 1.6; SizeY_mm: 0.8; SizeZ_mm: 1; EIA_Code: E24; U/M: EA; AEC Category: Q200
signal-integrity model Resistor
simulation model Resistor
footprint 0603
footprint 0603M
footprint 0603L
footprint 0603_HV
footprint 0603S
pins: 1, 2

## CRCW060393K1FKEA
designator R?  ValueDisplayed: 93.1k  (hidden comment: CRCW060393K1FKEA)
RES, 93.1 k, 1%, 0.1 W, 0603; Manufacturer: Vishay-Dale; CompType: Resistor; Value: 93.1k; Res_ohm: 93100; Value_Code: 93k1; Tolerance_%: 1; Power_W: 0.1; Value2: 0.1W; VDC_V: 75; TempCo: 100 ppm/C; SizeArea_mm2: 1.28; SizeX_mm: 1.6; SizeY_mm: 0.8; EIA_Code: E96; U/M: EA; AEC Category: Q200
signal-integrity model Resistor
simulation model Resistor
footprint 0603
footprint 0603M
footprint 0603L
footprint 0603_HV
footprint 0603S
pins: 1, 2

## CRCW060393R1FKEA
designator R?  ValueDisplayed: 93.1  (hidden comment: CRCW060393R1FKEA)
RES, 93.1, 1%, 0.1 W, 0603; Manufacturer: Vishay-Dale; CompType: Resistor; Value: 93.1; Value_Code: 93R1; Tolerance_%: 1; Power_W: 0.1; Value2: 0.1W; VDC_V: 75; TempCo: 100 ppm/C; SizeArea_mm2: 1.28; SizeX_mm: 1.6; SizeY_mm: 0.8; EIA_Code: E96; U/M: EA; AEC Category: Q200
signal-integrity model Resistor
simulation model Resistor
footprint 0603
footprint 0603M
footprint 0603L
footprint 0603_HV
footprint 0603S
pins: 1, 2

## CRCW060395K3FKEA
designator R?  ValueDisplayed: 95.3k  (hidden comment: CRCW060395K3FKEA)
RES, 95.3 k, 1%, 0.1 W, 0603; Manufacturer: Vishay-Dale; CompType: Resistor; Value: 95.3k; Res_ohm: 95300; Value_Code: 95k3; Tolerance_%: 1; Power_W: 0.1; Value2: 0.1W; VDC_V: 75; TempCo: 100 ppm/C; SizeArea_mm2: 1.28; SizeX_mm: 1.6; SizeY_mm: 0.8; EIA_Code: E96; U/M: EA; AEC Category: Q200; Green_Lifecycle: Active; Green_REACh: Passed
signal-integrity model Resistor
simulation model Resistor
footprint 0603
footprint 0603M
footprint 0603L
footprint 0603_HV
footprint 0603S
pins: 1, 2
